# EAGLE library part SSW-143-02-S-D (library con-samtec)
THROUGH-HOLE .025" SQ POST SOCKET Source: Samtec SSW.pdf
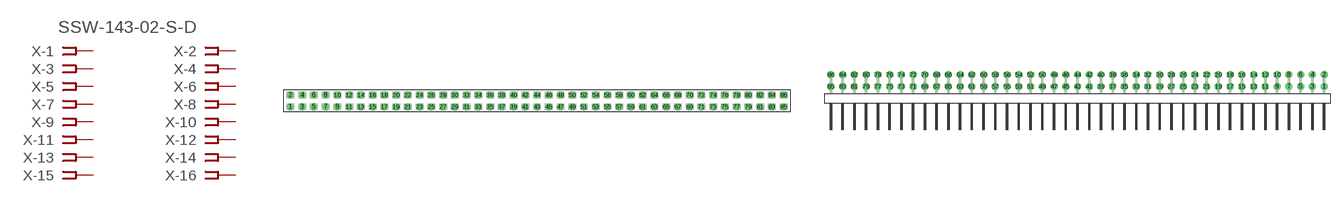
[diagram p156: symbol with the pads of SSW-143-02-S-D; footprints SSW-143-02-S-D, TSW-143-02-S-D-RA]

Designator prefix X; gates -1=FPINV -2=FPIN -3=FPIN -4=FPIN -5=FPIN -6=FPIN -7=FPIN -8=FPIN -9=FPIN -10=FPIN -11=FPIN -12=FPIN -13=FPIN -14=FPIN -15=FPIN -16=FPIN -17=FPIN -18=FPIN -19=FPIN -20=FPIN -21=FPIN -22=FPIN -23=FPIN -24=FPIN -25=FPIN -26=FPIN -27=FPIN -28=FPIN -29=FPIN -30=FPIN -31=FPIN -32=FPIN -33=FPIN -34=FPIN -35=FPIN -36=FPIN -37=FPIN -38=FPIN -39=FPIN -40=FPIN -41=FPIN -42=FPIN -43=FPIN -44=FPIN -45=FPIN -46=FPIN -47=FPIN -48=FPIN -49=FPIN -50=FPIN -51=FPIN -52=FPIN -53=FPIN -54=FPIN -55=FPIN -56=FPIN -57=FPIN -58=FPIN -59=FPIN -60=FPIN -61=FPIN -62=FPIN -63=FPIN -64=FPIN -65=FPIN -66=FPIN -67=FPIN -68=FPIN -69=FPIN -70=FPIN -71=FPIN -72=FPIN -73=FPIN -74=FPIN -75=FPIN -76=FPIN -77=FPIN -78=FPIN -79=FPIN -80=FPIN -81=FPIN -82=FPIN -83=FPIN -84=FPIN -85=FPIN -86=FPIN

## SSW-143-02-S-D (OC_FARNELL: unknown; OC_NEWARK: unknown)  [SSW-143-02-S-D]
1  -1:1  pas
2  -2:1  pas
3  -3:1  pas
4  -4:1  pas
5  -5:1  pas
6  -6:1  pas
7  -7:1  pas
8  -8:1  pas
9  -9:1  pas
10  -10:1  pas
11  -11:1  pas
12  -12:1  pas
13  -13:1  pas
14  -14:1  pas
15  -15:1  pas
16  -16:1  pas
17  -17:1  pas
18  -18:1  pas
19  -19:1  pas
20  -20:1  pas
21  -21:1  pas
22  -22:1  pas
23  -23:1  pas
24  -24:1  pas
25  -25:1  pas
26  -26:1  pas
27  -27:1  pas
28  -28:1  pas
29  -29:1  pas
30  -30:1  pas
31  -31:1  pas
32  -32:1  pas
33  -33:1  pas
34  -34:1  pas
35  -35:1  pas
36  -36:1  pas
37  -37:1  pas
38  -38:1  pas
39  -39:1  pas
40  -40:1  pas
41  -41:1  pas
42  -42:1  pas
43  -43:1  pas
44  -44:1  pas
45  -45:1  pas
46  -46:1  pas
47  -47:1  pas
48  -48:1  pas
49  -49:1  pas
50  -50:1  pas
51  -51:1  pas
52  -52:1  pas
53  -53:1  pas
54  -54:1  pas
55  -55:1  pas
56  -56:1  pas
57  -57:1  pas
58  -58:1  pas
59  -59:1  pas
60  -60:1  pas
61  -61:1  pas
62  -62:1  pas
63  -63:1  pas
64  -64:1  pas
65  -65:1  pas
66  -66:1  pas
67  -67:1  pas
68  -68:1  pas
69  -69:1  pas
70  -70:1  pas
71  -71:1  pas
72  -72:1  pas
73  -73:1  pas
74  -74:1  pas
75  -75:1  pas
76  -76:1  pas
77  -77:1  pas
78  -78:1  pas
79  -79:1  pas
80  -80:1  pas
81  -81:1  pas
82  -82:1  pas
83  -83:1  pas
84  -84:1  pas
85  -85:1  pas
86  -86:1  pas

## SSW-143-02-S-D-RA (MPN: SSW-143-02-S-D-RA; OC_FARNELL: unknown; OC_NEWARK: 11P9989)  [TSW-143-02-S-D-RA]
Pads as for SSW-143-02-S-D

## Footprint SSW-143-02-S-D (pad centres in mm)
THROUGH-HOLE .025" SQ POST SOCKET Source: Samtec SSW.pdf
drill 1 pad 1.5 octagon: 1 -53.34,-1.27; 2 -53.34,1.27; 3 -50.8,-1.27; 4 -50.8,1.27; 5 -48.26,-1.27; 6 -48.26,1.27; 7 -45.72,-1.27; 8 -45.72,1.27; 9 -43.18,-1.27; 10 -43.18,1.27; 11 -40.64,-1.27; 12 -40.64,1.27; 13 -38.1,-1.27; 14 -38.1,1.27; 15 -35.56,-1.27; 16 -35.56,1.27; 17 -33.02,-1.27; 18 -33.02,1.27; 19 -30.48,-1.27; 20 -30.48,1.27; 21 -27.94,-1.27; 22 -27.94,1.27; 23 -25.4,-1.27; 24 -25.4,1.27; 25 -22.86,-1.27; 26 -22.86,1.27; 27 -20.32,-1.27; 28 -20.32,1.27; 29 -17.78,-1.27; 30 -17.78,1.27; 31 -15.24,-1.27; 32 -15.24,1.27; 33 -12.7,-1.27; 34 -12.7,1.27; 35 -10.16,-1.27; 36 -10.16,1.27; 37 -7.62,-1.27; 38 -7.62,1.27; 39 -5.08,-1.27; 40 -5.08,1.27; 41 -2.54,-1.27; 42 -2.54,1.27; 43 0,-1.27; 44 0,1.27; 45 2.54,-1.27; 46 2.54,1.27; 47 5.08,-1.27; 48 5.08,1.27; 49 7.62,-1.27; 50 7.62,1.27; 51 10.16,-1.27; 52 10.16,1.27; 53 12.7,-1.27; 54 12.7,1.27; 55 15.24,-1.27; 56 15.24,1.27; 57 17.78,-1.27; 58 17.78,1.27; 59 20.32,-1.27; 60 20.32,1.27; 61 22.86,-1.27; 62 22.86,1.27; 63 25.4,-1.27; 64 25.4,1.27; 65 27.94,-1.27; 66 27.94,1.27; 67 30.48,-1.27; 68 30.48,1.27; 69 33.02,-1.27; 70 33.02,1.27; 71 35.56,-1.27; 72 35.56,1.27; 73 38.1,-1.27; 74 38.1,1.27; 75 40.64,-1.27; 76 40.64,1.27; 77 43.18,-1.27; 78 43.18,1.27; 79 45.72,-1.27; 80 45.72,1.27; 81 48.26,-1.27; 82 48.26,1.27; 83 50.8,-1.27; 84 50.8,1.27; 85 53.34,-1.27; 86 53.34,1.27

## Footprint TSW-143-02-S-D-RA (pad centres in mm)
THROUGH-HOLE .025" SQ POST HEADER Source: Samtec TSW.pdf
drill 1 pad 1.5 octagon: 1 53.34,1.524; 2 53.34,4.064; 3 50.8,1.524; 4 50.8,4.064; 5 48.26,1.524; 6 48.26,4.064; 7 45.72,1.524; 8 45.72,4.064; 9 43.18,1.524; 10 43.18,4.064; 11 40.64,1.524; 12 40.64,4.064; 13 38.1,1.524; 14 38.1,4.064; 15 35.56,1.524; 16 35.56,4.064; 17 33.02,1.524; 18 33.02,4.064; 19 30.48,1.524; 20 30.48,4.064; 21 27.94,1.524; 22 27.94,4.064; 23 25.4,1.524; 24 25.4,4.064; 25 22.86,1.524; 26 22.86,4.064; 27 20.32,1.524; 28 20.32,4.064; 29 17.78,1.524; 30 17.78,4.064; 31 15.24,1.524; 32 15.24,4.064; 33 12.7,1.524; 34 12.7,4.064; 35 10.16,1.524; 36 10.16,4.064; 37 7.62,1.524; 38 7.62,4.064; 39 5.08,1.524; 40 5.08,4.064; 41 2.54,1.524; 42 2.54,4.064; 43 0,1.524; 44 0,4.064; 45 -2.54,1.524; 46 -2.54,4.064; 47 -5.08,1.524; 48 -5.08,4.064; 49 -7.62,1.524; 50 -7.62,4.064; 51 -10.16,1.524; 52 -10.16,4.064; 53 -12.7,1.524; 54 -12.7,4.064; 55 -15.24,1.524; 56 -15.24,4.064; 57 -17.78,1.524; 58 -17.78,4.064; 59 -20.32,1.524; 60 -20.32,4.064; 61 -22.86,1.524; 62 -22.86,4.064; 63 -25.4,1.524; 64 -25.4,4.064; 65 -27.94,1.524; 66 -27.94,4.064; 67 -30.48,1.524; 68 -30.48,4.064; 69 -33.02,1.524; 70 -33.02,4.064; 71 -35.56,1.524; 72 -35.56,4.064; 73 -38.1,1.524; 74 -38.1,4.064; 75 -40.64,1.524; 76 -40.64,4.064; 77 -43.18,1.524; 78 -43.18,4.064; 79 -45.72,1.524; 80 -45.72,4.064; 81 -48.26,1.524; 82 -48.26,4.064; 83 -50.8,1.524; 84 -50.8,4.064; 85 -53.34,1.524; 86 -53.34,4.064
